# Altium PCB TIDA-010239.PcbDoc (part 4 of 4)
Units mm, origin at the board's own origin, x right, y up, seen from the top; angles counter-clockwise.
Board outline 160 x 175 mm, 4 copper layers (Top Layer, Inside 1, Inside 2, Bottom Layer), stack 1.787 mm thick; 299 components, 146 nets, 710 pads, 164 vias.
Unrouted connection lines stored in the file: 9.
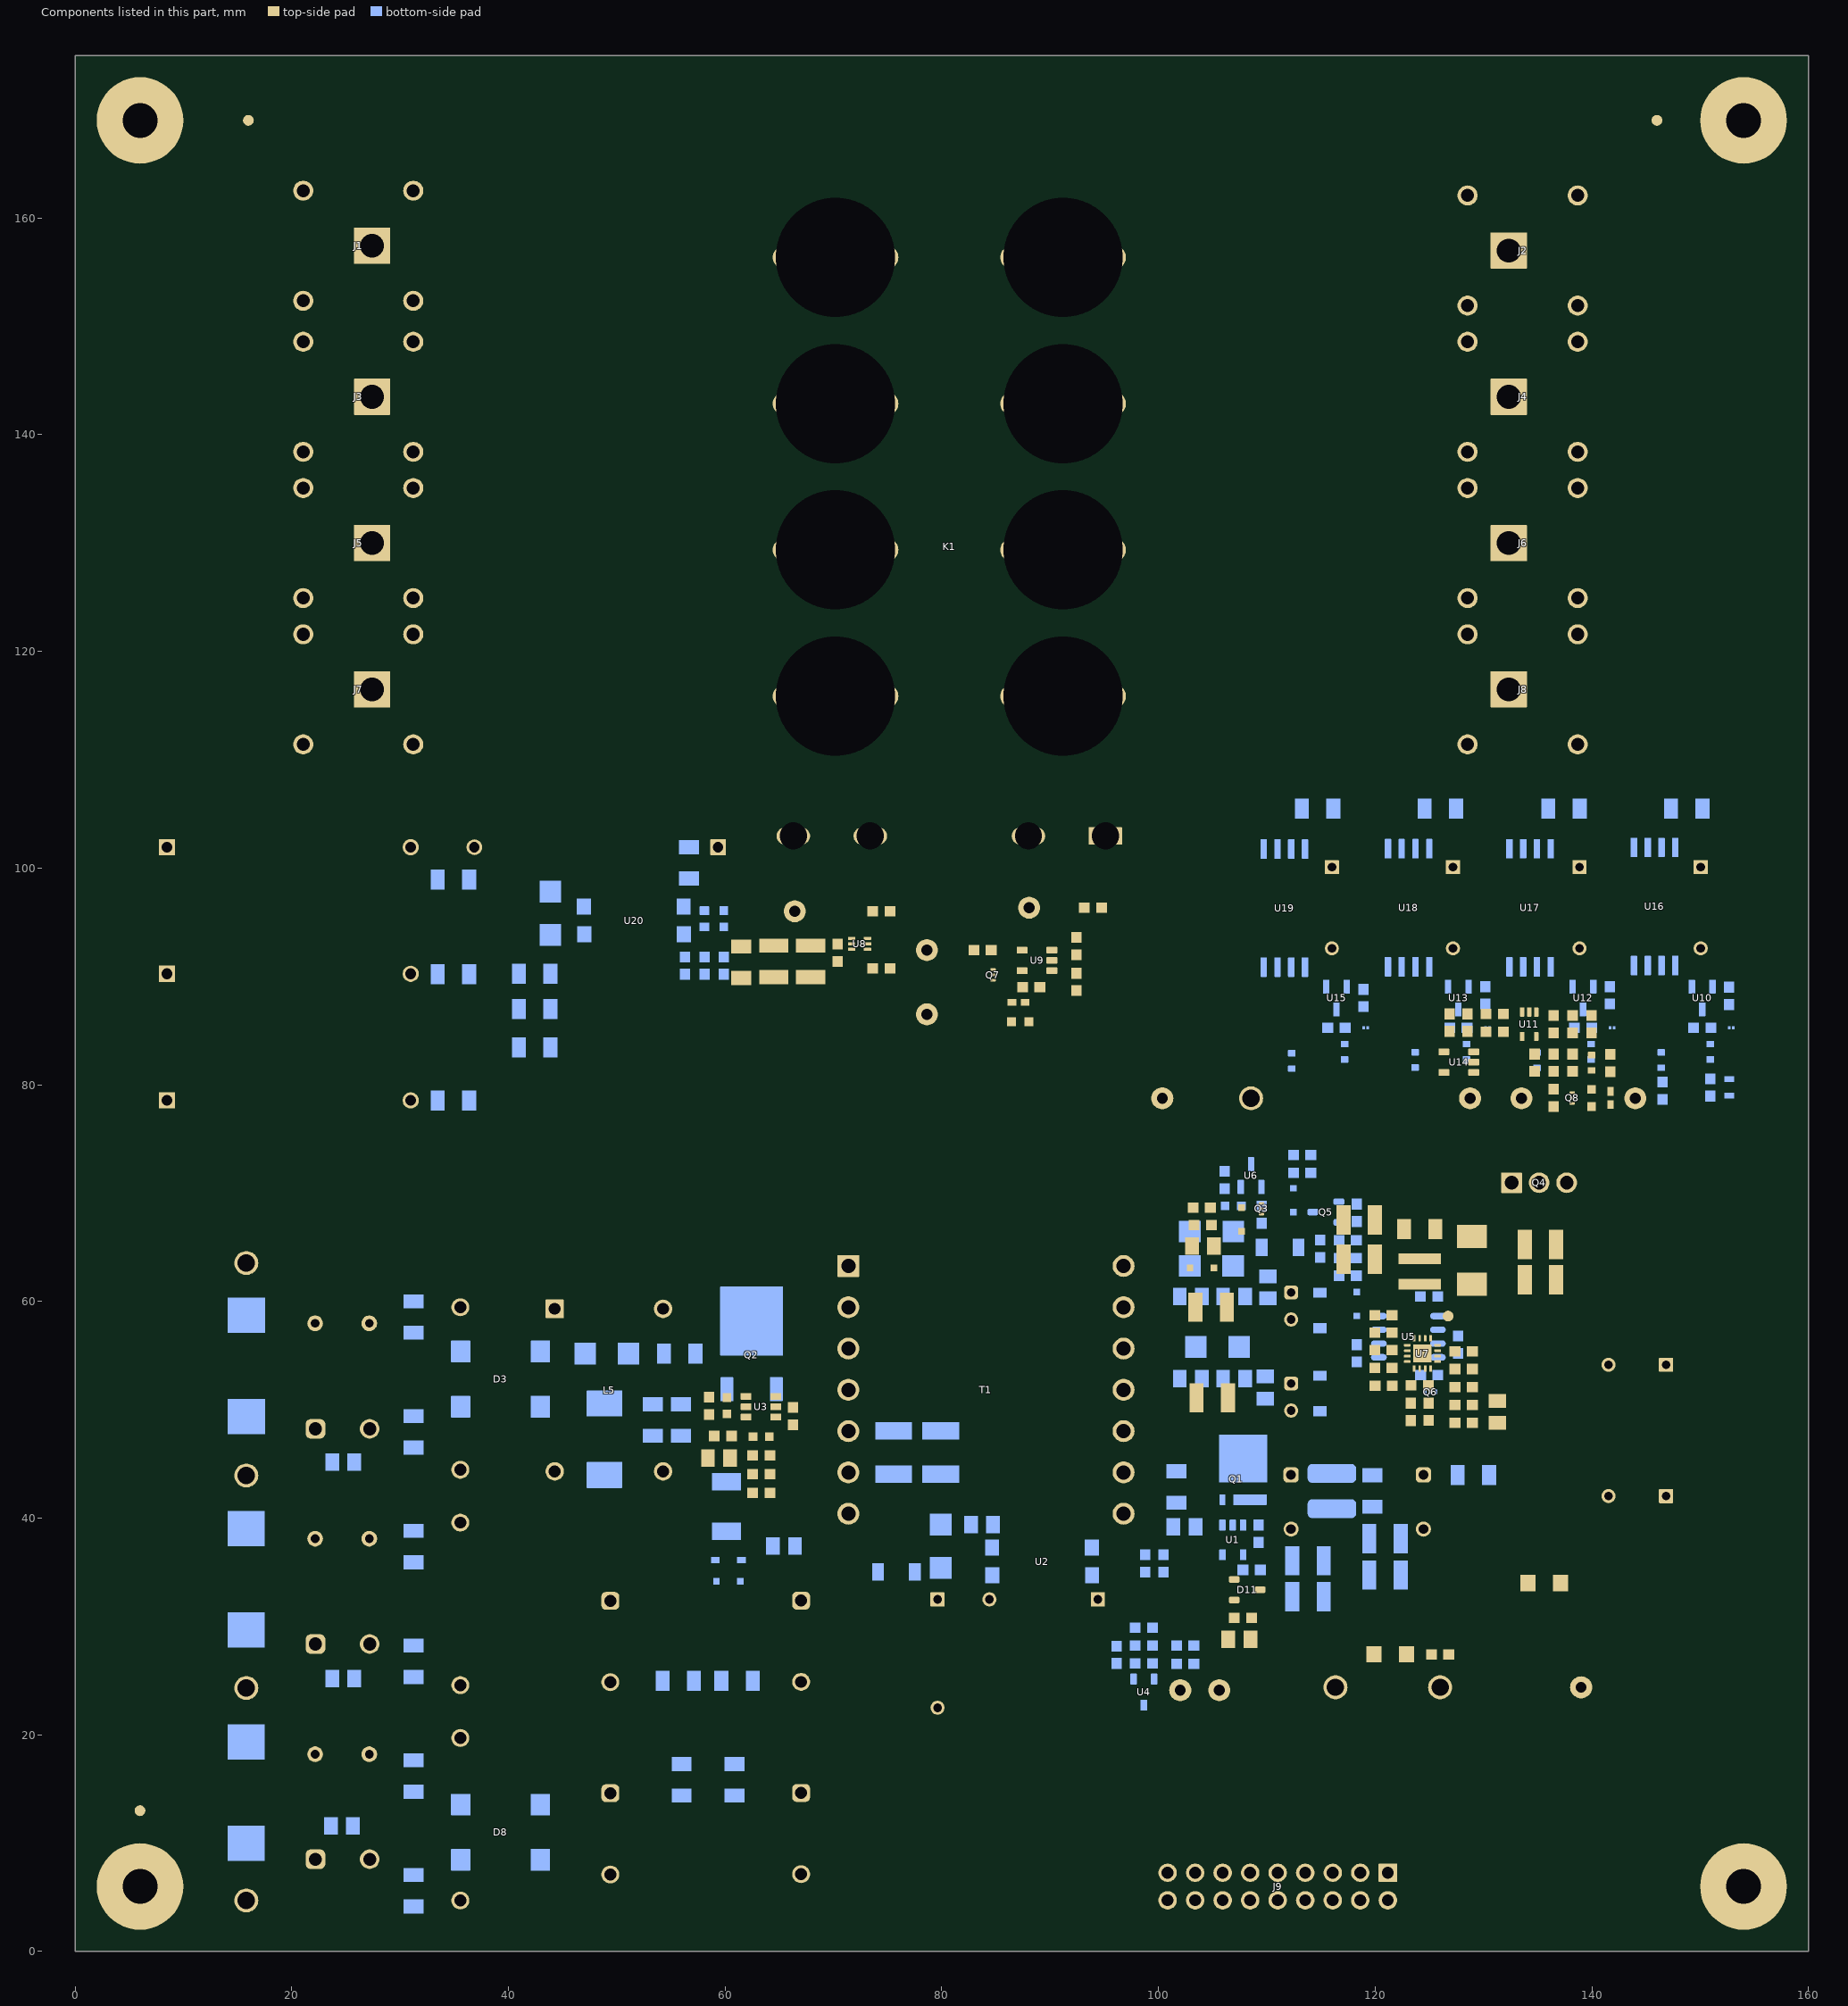
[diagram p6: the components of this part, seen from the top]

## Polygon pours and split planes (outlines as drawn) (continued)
LINE2_IN on Inside 1 "INSIDE_1_LINE2_IN_P040" (solid, remove dead copper, pour order 40): 76.25,139.5 77.5,140.75 77.5,148.25 76.25,149.5 35.25,149.5 32.75,147 25,147 23.75,145.75 23.75,140.75 25,139.5
LINE3_IN on Inside 1 "INSIDE_1_LINE3_IN_P036" (solid, remove dead copper, pour order 36): 76.541,126.143 77.791,127.393 77.791,134.893 76.541,136.143 35.622,136.143 33.122,133.643 25.291,133.643 24.041,132.393 24.041,127.393 25.291,126.143
N_IN on Inside 1 "INSIDE_1_N_IN_P030" (solid, remove dead copper, pour order 30): 76.25,112.5 77.5,113.75 77.5,121.25 76.25,122.5 35.216,122.5 32.716,120 25,120 23.75,118.75 23.75,113.75 25,112.5
NetD3_2 on Inside 1 "INSIDE_1_NETD3_2_P023" (solid, remove dead copper, pour order 23): 43.548,10.02 43.548,7.17 43.218,6.84 40.218,6.84 39.918,7.14 39.918,9.72 40.218,10.02
GND on Inside 1 "INSIDE_1_GND_P015" (solid, remove dead copper, pour order 15): 48.296,52.987 46.796,51.487 46.796,3.452 47.841,2.407 79.556,2.407 80.486,3.337 80.486,41.253 79.654,42.157 67.911,42.157 67.289,42.585 67.268,52.248 66.529,52.987
AGND2 on Inside 2 "INSIDE_2_AGND2_P022" (solid, remove dead copper, pour order 22): 119.34,58.5 119.34,49.274 119.75,48.75 121.25,48.75 121.75,48.25 121.75,46.75 122,46.5 122.092,46.592 132.06,46.592 132.06,49.758 129.564,49.758 129.564,57.936 129,58.5
PGND on Inside 2 "INSIDE_2_PGND_P079" (solid, remove dead copper, pour order 79): 98.08,-0.001 98.082,-0.001 ccw(c98.081,-0.001) 98.081,0 160,0 160,91.75 ccw(c159.25,91.75) 159.25,92.5 103.79,92.5 cw(c103.79,95.04) 101.25,95.04 101.25,102.75 ccw(c99.5,102.75) 99.5,104.5 57.79,104.5 ccw(c57.79,101.96) 55.25,101.96 55.25,77.79 ccw(c57.79,77.79) 57.79,75.25 90.71,75.25 cw(c90.71,72.71) 93.25,72.71 93.5,2.5 ccw(c96,2.5) 96,0 98.081,0
N_OUT on Inside 2 "INSIDE_2_N_OUT_P078" (solid, remove dead copper, pour order 78): 134.25,112.5 135.75,114 135.75,118.75 134.25,120.25 126.75,120.25 124.5,122.5 85,122.5 83.75,121.25 83.75,113.75 85,112.5
LINE1_OUT on Inside 2 "INSIDE_2_LINE1_OUT_P062" (solid, remove dead copper, pour order 62): 134.25,153 135.75,154.5 135.75,159.25 134.25,160.75 126.75,160.75 124.5,163 85,163 83.75,161.75 83.75,154.25 85,153
LINE2_OUT on Inside 2 "INSIDE_2_LINE2_OUT_P061" (solid, remove dead copper, pour order 61): 134.25,139.5 135.75,141 135.75,145.75 134.25,147.25 126.75,147.25 124.5,149.5 85,149.5 83.75,148.25 83.75,140.75 85,139.5
LINE3_OUT on Inside 2 "INSIDE_2_LINE3_OUT_P060" (solid, remove dead copper, pour order 60): 134.25,126 135.75,127.5 135.75,132.25 134.25,133.75 126.75,133.75 124.5,136 85,136 83.75,134.75 83.75,127.25 85,126
LINE1_IN on Inside 2 "INSIDE_2_LINE1_IN_P059" (solid, remove dead copper, pour order 59): 76.25,153 77.5,154.25 77.5,161.75 76.25,163 34.75,163 33,161.25 25,161.25 23.75,160 23.75,154.25 25,153
LINE2_IN on Inside 2 "INSIDE_2_LINE2_IN_P043" (solid, remove dead copper, pour order 43): 76.25,139.5 77.5,140.75 77.5,148.25 76.25,149.5 35.25,149.5 32.75,147 25,147 23.75,145.75 23.75,140.75 25,139.5
LINE3_IN on Inside 2 "INSIDE_2_LINE3_IN_P038" (solid, remove dead copper, pour order 38): 76.556,126.142 77.806,127.392 77.806,134.892 76.556,136.142 35.306,136.142 32.806,133.642 25.306,133.642 24.056,132.392 24.056,127.392 25.306,126.142
N_IN on Inside 2 "INSIDE_2_N_IN_P035" (solid, remove dead copper, pour order 35): 76.25,112.5 77.5,113.75 77.5,121.25 76.25,122.5 35.216,122.5 32.716,120 25,120 23.75,118.75 23.75,113.75 25,112.5
N_IN on Inside 2 "INSIDE_2_N_IN_P031" (solid, remove dead copper, pour order 31): 34.665,10.03 34.305,9.67 34.305,7.18 34.635,6.85 37.635,6.85 37.935,7.15 37.935,9.73 37.635,10.03

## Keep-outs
Keep-Out Layer:
  text ".Layer_Name" at 13.399,-21.806 h1.52

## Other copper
Top Layer:
  text ".Layer_Name" at 13.399,-21.806 h1.52
Bottom Layer:
  text ".Layer_Name" at 13.399,-21.806 h1.52

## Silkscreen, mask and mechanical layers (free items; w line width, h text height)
Top Overlay:
  drawing of 41 lines, arcs and shapes, not listed
  text "AC INPUT" at 42.75,165.75 h1.52
  text "AC OUTPUT" at 106.25,165.75 h1.52
  text "L1" at 47,156.5 h1.52
  text "L1" at 111.866,156.458 h1.52
  text "L2" at 47,142.56 h1.52
  text "L2" at 111.866,142.518 h1.52
  text "L3" at 47,129.06 h1.52
  text "L3" at 111.866,129.018 h1.52
  text "N" at 47,116.31 h1.52
  text "N" at 111.866,116.268 h1.52
  text "'.PRJ_Number'.PCB_Rev" at 129.793,9.3 h2.75
  text ".Layer_Name" at 13.399,-21.806 h1.52
Bottom Overlay:
  lines w0.2: 129.777,67.943 129.777,52.073 140.479,52.073 140.479,67.943
  lines w1: 89.43,3.811 89.272,71.25 51.371,71.25 51.292,108.458 100.394,108.458 105.37,108.458 105.37,96.43 ; 105.586,96.43 155.922,96.43
  text ".Layer_Name" at 13.399,-21.806 h1.52
Top Paste:
  text ".Layer_Name" at 13.399,-21.806 h1.52
Bottom Paste:
  text ".Layer_Name" at 13.399,-21.806 h1.52
Top Solder:
  text ".Layer_Name" at 13.399,-21.806 h1.52
  text ".Layer_Name" at 13.399,-21.806 h1.52
Bottom Solder:
  text ".Layer_Name" at 13.399,-21.806 h1.52
Drill Guide:
  text ".Layer_Name" at 13.399,-21.806 h1.52
M1 Board Outline:
  the board outline again, w0.254
  text ".Layer_Name" at 13.399,-21.806 h1.52
M2 Board Dimensions:
  rectangle: 1.918,-10.16 11.443,-6.985
  rectangle: -1.257,-6.985 1.918,-3.81
  lines w0.178: -1.257,-10.16 24.143,-10.16 ; -1.257,-6.985 24.143,-6.985
  text ".Layer_Name" at 13.399,-21.806 h1.52
M3 3D STEP Top:
  text ".Layer_Name" at 13.399,-21.806 h1.52
M4 3D STEP Bottom:
  text ".Layer_Name" at 13.399,-21.806 h1.52
M5 Assembly Top:
  lines w0.254: -8.673,-23.626 158.967,-23.626 ; -8.673,-18.462 159.017,-18.462 ; -8.673,-13.297 -8.673,-28.791 93.054,-28.791 159.017,-28.791 159.017,-13.297 -8.661,-13.297 -8.661,-28.791 31.357,-28.791 ; 53.938,-28.791 53.938,-13.297 ; 86.119,-18.462 86.119,-13.297 ; 107.455,-18.462 107.455,-13.297 ; 123.254,-28.956 123.254,-23.804
  text "COMPONENTS MARKED 'DNP' SHOULD NOT BE POPULATED." at 28.042,-8.09 h1.52
  text "ASSEMBLY VARIANT:" at 28.03,-11.024 h1.52
  text ".VariantName" at 54.344,-11.024 h1.52
  text "PCB VIEWED FROM TOP SIDE" at -7.061,-16.654 h1.52
  text "BOARD #:" at 55.843,-16.654 h1.52
  text ".PRJ_Number" at 69.698,-16.654 h1.52
  text "REV:" at 91.149,-16.654 h1.52
  text ".PCB_Rev" at 98.553,-16.654 h1.52
  text "SVN REV:" at 112.434,-16.654 h1.52
  text ".VersionControl_RevNumber" at 125.286,-16.654 h1.52
  text "PLOT NAME =" at -7.061,-27.034 h1.52
  text ".plot_File_Name" at 13.399,-27.034 h1.52
  text "GENERATED    :" at 55.893,-27.034 h1.52
  text ".Print_Date" at 77.979,-27.034 h1.52
  text ".Print_Time" at 96.495,-27.034 h1.52
  text "TEXAS INSTRUMENTS" at 128.614,-27.034 h1.52
M6 Assembly Bottom:
  lines w0.254: -8.686,-18.474 159.005,-18.474 ; -8.635,-23.639 159.005,-23.639 ; 27.077,-28.969 27.077,-23.817 ; 42.876,-18.474 42.876,-13.31 ; 64.212,-18.474 64.212,-13.31 ; 96.394,-28.804 96.394,-13.31 ; 118.974,-28.804 158.992,-28.804 158.992,-13.31 -8.686,-13.31 -8.686,-28.804 57.278,-28.804 159.005,-28.804 159.005,-13.31
  text "COMPONENTS MARKED 'DNP' SHOULD NOT BE POPULATED." at 153.734,-8.077 h1.52
  text ".VariantName" at 127.217,-11.024 h1.52
  text "ASSEMBLY VARIANT:" at 153.607,-11.024 h1.52
  text ".VersionControl_RevNumber" at 25.045,-16.667 h1.52
  text "SVN REV:" at 37.897,-16.667 h1.52
  text ".PCB_Rev" at 51.779,-16.667 h1.52
  text "REV:" at 59.183,-16.667 h1.52
  text ".PRJ_Number" at 80.633,-16.667 h1.52
  text "BOARD #:" at 94.489,-16.667 h1.52
  text "PCB VIEWED FROM BOTTOM SIDE" at 157.392,-16.667 h1.52
  text "TEXAS INSTRUMENTS" at 21.718,-27.047 h1.52
  text ".Print_Time" at 53.836,-27.047 h1.52
  text ".Print_Date" at 72.353,-27.047 h1.52
  text "GENERATED    :" at 94.438,-27.047 h1.52
  text ".plot_File_Name" at 136.932,-27.047 h1.52
  text "PLOT NAME =" at 157.392,-27.047 h1.52
M9 Title Sheet:
  drawing of 63 lines, arcs and shapes, not listed
  text "1" at 34.037,466.75 h1.78
  text "2" at 135.51,466.75 h1.78
  text "3" at 236.983,466.75 h1.78
  text "4" at 338.608,466.75 h1.78
  text "5" at 440.166,466.75 h1.78
  text "6" at 541.724,466.75 h1.78
  text "7" at 643.366,466.75 h1.78
  text "8" at 744.839,466.75 h1.78
  text "A" at -13.131,405.841 h1.78
  text "A" at 792.049,405.841 h1.78
  text "B" at -13.131,278.841 h1.78
  text "B" at 792.049,278.841 h1.78
  text "C" at -13.131,151.841 h1.78
  text "C" at 792.049,151.841 h1.78
  text "D" at -13.131,24.841 h1.78
  text "D" at 792.049,24.841 h1.78
  text "PROJECT TITLE:" at 713.69,6.823 h1.14
  text ".PRJ_Title" at 714.96,3.436 h1.78
  text "DESIGNED FOR:" at 713.69,-0.823 h1.14
  text ".PRJ_Customer" at 714.96,-4.379 h1.78
  text "FILE NAME:" at 713.69,-8.443 h1.14
  text ".PCB_File_Name_No_Path" at 714.96,-11.491 h1.78
  text "Texas Instruments (TI) and/or its licensors do not warrant the accuracy or completeness of this specification" at 587.465,-15.601 h1.14
  text "ENGINEER:" at 713.69,-15.809 h1.14
  text "LAYOUT BY:" at 751.917,-15.809 h1.14
  text "or any information contained therein. TI and/or its licensors do not warrant that this design will meet" at 586.322,-18.463 h1.14
  text ".PRJ_Engineer" at 714.96,-19.746 h1.78
  text ".PCB_Layout" at 753.2,-19.746 h1.78
  text "the specifications, will be suitable for your application or fit for any particular purpose, or will operate in" at 586.322,-21.325 h1.14
  text ".Layer_Name" at 13.399,-21.806 h1.52
  text "ALTIUM DESIGNER VERSION:" at 751.917,-23.683 h1.14
  text "an implementation. TI and/or its licensors do not warrant that the design is production worthy. You should" at 586.322,-24.187 h1.14
  text "completely validate and test your design implementation to confirm the system functionality for your application." at 587.465,-27.048 h1.14
  text ".print_Scale" at 714.96,-27.069 h1.78
  text ".Application_BuildNumber" at 753.2,-27.069 h1.78
  text "1" at 34.037,-33.503 h1.78
  text "2" at 135.51,-33.503 h1.78
  text "3" at 236.983,-33.503 h1.78
  text "4" at 338.608,-33.503 h1.78
  text "5" at 440.166,-33.503 h1.78
  text "6" at 541.724,-33.503 h1.78
  text "7" at 643.366,-33.503 h1.78
  text "8" at 744.839,-33.503 h1.78
M10 Fab Notes:
  drawing of 189 lines, arcs and shapes, not listed
  text "DESIGN INFORMATION" at 740.119,161.675 h1.52
  text "MIN. TRACK WIDTH:" at 723.747,158.319 h1.52
  text "8" at 751.592,158.32 h1.52
  text "MIL" at 755.523,158.319 h1.52
  text "MIN. CLEARANCE:" at 723.747,155.167 h1.52
  text "7.874" at 747.243,155.167 h1.52
  text "MIL" at 755.523,155.167 h1.52
  text "MIN. VIA PAD SIZE:" at 723.747,152.014 h1.52
  text "24" at 750.83,152.014 h1.52
  text "MIL" at 755.523,152.014 h1.52
  text "0.05mm (2MIL)" at 741.4,148.714 h1.52
  text "MINIMUM ANNULAR RING" at 715.385,148.506 h1.52
  text "EXTERNAL" at 759.383,148.506 h1.52
  text "PER" at 720.465,145.708 h1.52
  text "IPC-D-275 CLASS 2 LEVEL C" at 726.053,145.708 h1.52
  text "MIL, HOLES" at 763.854,143.156 h1.52
  text "+/-" at 753.885,142.938 h1.52
  text "+/-" at 775.577,142.938 h1.52
  text "REGISTRATION TOLERANCES:" at 715.385,142.911 h1.52
  text "METAL" at 745.859,142.911 h1.52
  text "5" at 760.494,142.911 h1.52
  text "3" at 781.653,142.911 h1.52
  text "MIL" at 784.606,142.911 h1.52
  text "HOLE SIZE TOLERANCE (UNLESS OTHERWISE SPECIFIED):" at 715.385,140.414 h1.52
  text "+/-" at 775.577,140.341 h1.52
  text "3" at 781.653,140.314 h1.52
  text "MIL" at 784.606,140.314 h1.52
  text "MATERIAL:" at 713.486,136.818 h1.52
  text "FR-4 High Tg" at 738.541,133.553 h1.52
  text "X" at 734.873,133.35 h1.52
  text "FR-4" at 724.179,133.235 h1.52
  text "OTHER" at 761.974,133.235 h1.52
  text "62 MIL (1.6mm) +/-10%" at 732.31,129.602 h1.52
  text "X" at 729.259,129.54 h1.52
  text "THICKNESS:" at 715.385,129.394 h1.52
  text "OTHER" at 764.946,129.394 h1.52
  text "TOLERANCE:" at 715.385,125.88 h1.52
  text "X" at 736.93,125.88 h1.52
  text "ANSI IPC-6012 TYPE 3 CLASS 2" at 741.451,125.88 h1.52
  text "OTHER +/-" at 741.451,122.218 h1.52
  text "BOW & TWIST:" at 715.385,118.53 h1.52
  text "X" at 736.93,118.53 h1.52
  text "ANSI IPC-6012 TYPE 3 CLASS 2" at 741.451,118.53 h1.52
  text "OTHER +/-" at 741.451,114.804 h1.52
  text "DRILLING:" at 713.486,111.486 h1.52
  text "NC_DRILL FILES" at 758.215,108.815 h1.52
  text "REFERENCE:" at 715.385,108.715 h1.52
  text "X" at 732.079,108.712 h1.52
  text "AS SHOWN" at 736.6,108.715 h1.52
  text "X" at 754.964,108.715 h1.52
  text "OTHER" at 765.784,105.101 h1.52
  text "PTH COPPER THICKNESS:" at 715.377,105.012 h1.52
  text "X" at 744.313,105.012 h1.52
  text "20-30 um" at 747.564,105.012 h1.52
  text "BOARD FINISH:" at 713.486,101.263 h1.52
  text "SILKSCREEN:" at 717.428,98.466 h1.52
  text "X" at 741.756,98.466 h1.52
  text "TOP" at 744.728,98.466 h1.52
  text "X" at 754.71,98.466 h1.52
  text "BOTTOM" at 757.707,98.466 h1.52
  text "SILKSCREEN COLOR:" at 717.428,94.524 h1.52
  text "X" at 741.731,94.524 h1.52
  text "WHITE" at 744.728,94.524 h1.52
  text "OTHER" at 757.707,94.524 h1.52
  text "X" at 745.058,90.88 h1.52
  text "GREEN" at 748.055,90.88 h1.52
  text "OTHER" at 763.752,90.88 h1.52
  text "SOLDER RESIST COLOR:" at 717.428,90.706 h1.52
  text "X" at 745.058,86.962 h1.52
  text "MATTE" at 748.055,86.962 h1.52
  text "SEMI-GLOSS" at 763.741,86.946 h1.52
  text "IMMERSION GOLD (ENIG)" at 740.435,82.574 h1.52
  text "ENEPIG" at 774.409,82.39 h1.52
  text "SURFACE FINISH:" at 713.486,82.365 h1.52
  text "X" at 735.914,82.365 h1.52
  text "IMM. TIN/SILVER OR EQUIV" at 721.856,78.877 h1.52
  text "OTHER" at 758.215,78.777 h1.52
  text "ARRAY/PANEL:" at 713.486,74.831 h1.52
  text "CUT AND TRIM PER M1 BOARD OUTLINE" at 740.435,74.622 h1.52
  text "N.C. ROUTE" at 740.435,71.168 h1.52
  text "X" at 757.91,71.168 h1.52
  text "V. SCORE" at 762.431,71.168 h1.52
  text "CERTIFICATION:" at 713.486,67.888 h1.52
  text "MATERIALS AND WORKMANSHIP FOR ALL PCBS" at 731.901,67.888 h1.52
  text "TO MEET OR EXCEED THE REQUIREMENTS OF:" at 731.901,65.499 h1.52
  text "X" at 722.693,62.232 h1.52
  text "ANSI IPC-A-600F CLASS ->" at 725.944,62.232 h1.52
  text "X" at 767.804,62.232 h1.52
  text "2" at 770.598,62.232 h1.52
  text "1" at 762.597,62.194 h1.52
  text "3" at 779.589,62.194 h1.52
  text "X" at 743.318,58.481 h1.52
  text "RoHS" at 746.569,58.481 h1.52
  text "OTHER" at 762.937,58.481 h1.52
  text "PER ORDER" at 773.022,58.481 h1.52
  text "ALL BOARDS MUST MEET OR EXCEED UL94-V0 REQUIREMENTS." at 714.185,54.574 h1.52
  text "PCB MUST BEAR THE UL94V-0 UL REGISTERED MATERIAL ID NUMBER" at 714.185,51.626 h1.52
  text "ADDITIONAL REQUIREMENTS:" at 713.486,47.322 h1.52
  text "MICROSECTION:" at 715.385,44.601 h1.52
  text "YES" at 738.39,44.601 h1.52
  text "REQUIRED" at 760.272,40.935 h1.52
  text "BARE BOARD ELEC. TEST:" at 715.385,40.863 h1.52
  text "NONE" at 748.55,40.863 h1.52
  text "X" at 757.275,40.863 h1.52
  text "PER ORDER" at 775.309,40.863 h1.52
  text "XX MIL VIAS REQUIRE NON-CONDUCTIVE FILL AND PLANARIZE" at 719.656,35.657 h1.5
  text "XX MIL VIAS REQUIRE CONDUCTIVE FILL AND PLANARIZE" at 719.859,33.016 h1.52
  text "OUTER XX MIL TRACES REQUIRE 50 OHM SINGLE-ENDED IMPEDANCE" at 719.834,28.866 h1.47
  text "LAYER 2 & 3 (INNER LAYERS) XX MIL WIDE, XX MIL SPACE / TRACES REQUIRE 100 OHM DIFFERENTIAL IMPEDANCE" at 719.631,22.879 h1.52
  text ".Layer_Name" at 13.399,-21.806 h1.52
M11 Gerber Information:
  lines w0.254: -8.673,-23.626 158.967,-23.626 ; -8.673,-18.462 159.017,-18.462 ; -8.673,-13.297 -8.673,-28.791 93.054,-28.791 159.017,-28.791 159.017,-13.297 -8.661,-13.297 -8.661,-28.791 31.357,-28.791 ; 53.938,-28.791 53.938,-13.297 ; 86.119,-18.462 86.119,-13.297 ; 107.455,-18.462 107.455,-13.297 ; 123.254,-28.956 123.254,-23.804
  text "ALL ARTWORK VIEWED FROM TOP SIDE" at -7.061,-16.654 h1.52
  text "BOARD #:" at 55.843,-16.654 h1.52
  text ".PRJ_Number" at 69.698,-16.654 h1.52
  text "REV:" at 91.149,-16.654 h1.52
  text ".PCB_Rev" at 98.553,-16.654 h1.52
  text "SVN REV:" at 112.434,-16.654 h1.52
  text ".VersionControl_RevNumber" at 125.286,-16.654 h1.52
  text "LAYER NAME =" at -7.061,-21.806 h1.52
  text "PLOT NAME =" at -7.061,-27.034 h1.52
  text ".plot_File_Name" at 13.399,-27.034 h1.52
  text "GENERATED    :" at 55.893,-27.034 h1.52
  text ".Print_Date" at 77.979,-27.034 h1.52
  text ".Print_Time" at 96.495,-27.034 h1.52
  text "TEXAS INSTRUMENTS" at 128.614,-27.034 h1.52
M12 Stackup:
  drawing of 295 lines, arcs and shapes, not listed
  text "Layer" at 673.212,457.523 h1.52
  text "Name" at 683.624,457.523 h1.52
  text "Material" at 707.239,457.523 h1.52
  text "Thickness" at 729.077,457.523 h1.52
  text "Constant" at 745.583,457.523 h1.52
  text "Board Layer Stack" at 760.058,457.523 h1.52
  text "Top Overlay" at 683.624,454.475 h1.52
  text "Top Solder" at 683.624,451.427 h1.52
  text "Solder Resist" at 707.239,451.427 h1.52
  text "0.40mil" at 729.077,451.427 h1.52
  text "3.5" at 745.583,451.427 h1.52
  text "1" at 673.212,448.379 h1.52
  text "Top Layer" at 683.624,448.379 h1.52
  text "1.40mil" at 729.077,448.379 h1.52
  text "Dielectric 1" at 683.624,445.331 h1.52
  text "PP-006" at 707.239,445.331 h1.52
  text "2.80mil" at 729.077,445.331 h1.52
  text "4.1" at 745.583,445.331 h1.52
  text "2" at 673.212,442.283 h1.52
  text "Inside 1" at 683.624,442.283 h1.52
  text "CF-004" at 707.239,442.283 h1.52
  text "1.38mil" at 729.077,442.283 h1.52
  text "Dielectric1" at 683.624,439.235 h1.52
  text "FR-4 High Tg" at 707.239,439.235 h1.52
  text "59.20mil" at 729.077,439.235 h1.52
  text "4.8" at 745.583,439.235 h1.52
  text "3" at 673.212,436.187 h1.52
  text "Inside 2" at 683.624,436.187 h1.52
  text "CF-004" at 707.239,436.187 h1.52
  text "1.38mil" at 729.077,436.187 h1.52
  text "Dielectric 2" at 683.624,433.139 h1.52
  text "PP-006" at 707.239,433.139 h1.52
  text "2.80mil" at 729.077,433.139 h1.52
  text "4.1" at 745.583,433.139 h1.52
  text "4" at 673.212,430.091 h1.52
  text "Bottom Layer" at 683.624,430.091 h1.52
  text "1.40mil" at 729.077,430.091 h1.52
  text "Bottom Solder" at 683.624,427.043 h1.52
  text "Solder Resist" at 707.239,427.043 h1.52
  text "0.40mil" at 729.077,427.043 h1.52
  text "3.5" at 745.583,427.043 h1.52
  text "Bottom Overlay" at 683.624,423.995 h1.52
  text ".Layer_Name" at 13.399,-21.806 h1.52
M13 Component Bodies Top:
  text ".Layer_Name" at 13.399,-21.806 h1.52
M14 Component Bodies Bottom:
  text ".Layer_Name" at 13.399,-21.806 h1.52
M15 Courtyards Top:
  text ".Layer_Name" at 13.399,-21.806 h1.52
M16 Courtyards Bottom:
  text ".Layer_Name" at 13.399,-21.806 h1.52
Drill Drawing:
  circle w0.254: c178.755,55.264 r0.421
  circle w0.254: c178.755,55.264 r0.702
  circle w0.254: c178.755,33.16 r0.702
  lines w0.254: 178.053,26.143 178.053,26.494 178.404,26.844 178.053,27.195 178.053,27.546 178.404,27.546 178.755,27.195 179.106,27.546 179.457,27.546 179.457,27.195 179.106,26.844 179.457,26.494 179.457,26.143 179.106,26.143 178.755,26.494 178.404,26.143 178.053,26.143 ; 178.053,29.651 178.404,29.651 178.755,29.3 179.106,29.651 179.457,29.651 179.106,30.002 179.457,30.353 179.106,30.353 178.755,30.704 178.404,30.353 178.053,30.353 178.404,30.002 178.053,29.651 ; 178.053,39.125 178.404,39.125 178.404,38.774 179.106,38.774 179.106,39.125 179.457,39.125 179.457,39.826 179.106,39.826 179.106,40.177 178.404,40.177 178.404,39.826 178.053,39.826 178.053,39.125 ; 178.053,41.931 178.755,42.282 179.457,41.931 179.106,42.633 179.457,43.335 178.755,42.984 178.053,43.335 178.404,42.633 178.053,41.931 ; 178.053,46.493 179.457,46.493 178.755,45.089 178.053,46.493 ; 178.053,64.035 179.457,64.035 179.457,65.439 178.053,65.439 178.053,64.035 ; 178.053,68.597 179.457,68.597 178.755,67.193 178.053,68.597 ; 178.334,26.423 178.334,26.634 178.544,26.844 178.334,27.055 178.334,27.266 178.544,27.266 178.755,27.055 178.966,27.266 179.176,27.266 179.176,27.055 178.966,26.844 179.176,26.634 179.176,26.423 178.966,26.423 178.755,26.634 178.544,26.423 178.334,26.423 ; 178.334,68.316 179.176,68.316 178.755,67.474 178.334,68.316
  lines w0.305: 176.781,25.195 258.861,25.195 ; 176.781,85.192 258.861,85.192 ; 185.363,22.038 185.363,88.35 ; 193.795,22.038 193.795,88.35 ; 209.964,22.038 209.964,88.35 ; 216.546,22.038 216.546,88.35 ; 226.075,22.038 226.075,88.35 ; 244.473,22.038 244.473,88.35 ; 176.781,22.038 258.861,22.038 258.861,88.35 176.781,88.35 176.781,22.038
  text "Symbol" at 178.676,86.14 h1.83
  text "Quantity" at 186.31,86.14 h1.83
  text "Finished Hole Size" at 194.743,86.14 h1.83
  text "Plated" at 210.912,86.14 h1.83
  text "Hole Type" at 217.494,86.14 h1.83
  text "Drill Layer Pair" at 227.023,86.14 h1.83
  text "Hole Tolerance" at 245.421,86.14 h1.83
  text "4" at 186.31,82.982 h1.52
  text "86.61mil (2.200mm)" at 194.743,82.982 h1.52
  text "NPTH" at 210.912,82.982 h1.52
  text "Round" at 217.494,82.982 h1.52
  text "Top Layer - Bottom Layer" at 227.023,82.982 h1.52
  text "K" at 178.033,82.728 h1.4
  text "4" at 186.31,79.824 h1.52
  text "10.00mil (0.254mm)" at 194.743,79.824 h1.52
  text "PTH" at 210.912,79.824 h1.52
  text "Round" at 217.494,79.824 h1.52
  text "Top Layer - Bottom Layer" at 227.023,79.824 h1.52
  text "E" at 178.033,79.57 h1.4
  text "118" at 186.31,76.666 h1.52
  text "12.00mil (0.305mm)" at 194.743,76.666 h1.52
  text "PTH" at 210.912,76.666 h1.52
  text "Round" at 217.494,76.666 h1.52
  text "Top Layer - Bottom Layer" at 227.023,76.666 h1.52
  text "G" at 178.033,76.413 h1.4
  text "7" at 186.31,73.509 h1.52
  text "16.00mil (0.406mm)" at 194.743,73.509 h1.52
  text "PTH" at 210.912,73.509 h1.52
  text "Round" at 217.494,73.509 h1.52
  text "Top Layer - Bottom Layer" at 227.023,73.509 h1.52
  text "F" at 178.033,73.255 h1.4
  text "35" at 186.31,70.351 h1.52
  text "25.00mil (0.635mm)" at 194.743,70.351 h1.52
  text "PTH" at 210.912,70.351 h1.52
  text "Round" at 217.494,70.351 h1.52
  text "Top Layer - Bottom Layer" at 227.023,70.351 h1.52
  text "D" at 178.033,70.097 h1.4
  text "26" at 186.31,67.193 h1.52
  text "31.50mil (0.800mm)" at 194.743,67.193 h1.52
  text "PTH" at 210.912,67.193 h1.52
  text "Round" at 217.494,67.193 h1.52
  text "Top Layer - Bottom Layer" at 227.023,67.193 h1.52
  text "4" at 186.31,64.035 h1.52
  text "35.43mil (0.900mm)" at 194.743,64.035 h1.52
  text "PTH" at 210.912,64.035 h1.52
  text "Round" at 217.494,64.035 h1.52
  text "Top Layer - Bottom Layer" at 227.023,64.035 h1.52
  text "2" at 186.31,60.878 h1.52
  text "37.40mil (0.950mm)" at 194.743,60.878 h1.52
  text "PTH" at 210.912,60.878 h1.52
  text "Round" at 217.494,60.878 h1.52
  text "Top Layer - Bottom Layer" at 227.023,60.878 h1.52
  text "B" at 178.033,60.624 h1.4
  text "6" at 186.31,57.72 h1.52
  text "39.37mil (1.000mm)" at 194.743,57.72 h1.52
  text "PTH" at 210.912,57.72 h1.52
  text "Round" at 217.494,57.72 h1.52
  text "Top Layer - Bottom Layer" at 227.023,57.72 h1.52
  text "A" at 178.033,57.466 h1.4
  text "11" at 186.31,54.562 h1.52
  text "40.00mil (1.016mm)" at 194.743,54.562 h1.52
  text "PTH" at 210.912,54.562 h1.52
  text "Round" at 217.494,54.562 h1.52
  text "Top Layer - Bottom Layer" at 227.023,54.562 h1.52
  text "36" at 186.31,51.405 h1.52
  text "43.31mil (1.100mm)" at 194.743,51.405 h1.52
  text "PTH" at 210.912,51.405 h1.52
  text "Round" at 217.494,51.405 h1.52
  text "Top Layer - Bottom Layer" at 227.023,51.405 h1.52
  text "C" at 178.033,51.151 h1.4
  text "38" at 186.31,48.247 h1.52
  text "47.24mil (1.200mm)" at 194.743,48.247 h1.52
  text "PTH" at 210.912,48.247 h1.52
  text "Round" at 217.494,48.247 h1.52
  text "Top Layer - Bottom Layer" at 227.023,48.247 h1.52
  text "H" at 178.033,47.993 h1.4
  text "3" at 186.31,45.089 h1.52
  text "49.21mil (1.250mm)" at 194.743,45.089 h1.52
  text "PTH" at 210.912,45.089 h1.52
  text "Round" at 217.494,45.089 h1.52
  text "Top Layer - Bottom Layer" at 227.023,45.089 h1.52
  text "14" at 186.31,41.931 h1.52
  text "51.97mil (1.320mm)" at 194.743,41.931 h1.52
  text "PTH" at 210.912,41.931 h1.52
  text "Round" at 217.494,41.931 h1.52
  text "Top Layer - Bottom Layer" at 227.023,41.931 h1.52
  text "7" at 186.31,38.774 h1.52
  text "63.00mil (1.600mm)" at 194.743,38.774 h1.52
  text "PTH" at 210.912,38.774 h1.52
  text "Round" at 217.494,38.774 h1.52
  text "Top Layer - Bottom Layer" at 227.023,38.774 h1.52
  text "4" at 186.31,35.616 h1.52
  text "86.61mil (2.200mm)" at 194.743,35.616 h1.52
  text "PTH" at 210.912,35.616 h1.52
  text "Round" at 217.494,35.616 h1.52
  text "Top Layer - Bottom Layer" at 227.023,35.616 h1.52
  text "I" at 178.267,35.362 h1.4
  text "4" at 186.31,32.458 h1.52
  text "125.98mil (3.200mm)" at 194.743,32.458 h1.52
  text "PTH" at 210.912,32.458 h1.52
  text "Round" at 217.494,32.458 h1.52
  text "Top Layer - Bottom Layer" at 227.023,32.458 h1.52
  text "4" at 186.31,29.3 h1.52
  text "98.43mil (2.500mm)" at 194.743,29.3 h1.52
  text "PTH" at 210.912,29.3 h1.52
  text "Slot" at 217.494,29.3 h1.52
  text "Top Layer - Bottom Layer" at 227.023,29.3 h1.52
  text "8" at 186.31,26.143 h1.52
  text "433.07mil (11.000mm)" at 194.743,26.143 h1.52
  text "PTH" at 210.912,26.143 h1.52
  text "Slot" at 217.494,26.143 h1.52
  text "Top Layer - Bottom Layer" at 227.023,26.143 h1.52
  text "335 Total" at 186.31,22.985 h1.52
  text "Slot definitions :" at 178.676,20.775 h1.52
  text "Routed Path Length" at 190.124,20.775 h1.52
  text "= Calculated from tool start centre position to tool end centre position." at 203.833,20.775 h1.52
  text "Hole Length" at 190.124,19.512 h1.52
  text "= Routed Path Length + Tool Size = Slot length as defined in the PCB layout" at 198.758,19.512 h1.52
  text ".Layer_Name" at 13.399,-21.806 h1.52
M17 Embedded Cavity:
  text ".Layer_Name" at 13.399,-21.806 h1.52
M18 Embedded Assembly:
  text ".Layer_Name" at 13.399,-21.806 h1.52
M19 Embedded Keepout:
  text ".Layer_Name" at 13.653,-21.552 h1.52

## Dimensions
160,0 to 0,0 on M2 Board Dimensions
0,175 to 0,0 on M2 Board Dimensions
